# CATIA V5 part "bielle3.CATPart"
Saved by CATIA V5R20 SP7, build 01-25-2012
Part number: bielle3
Publications: "droite_bielle_3", "droite_pivot_3_2", "droite_pivot_3_0"
Bounding box of the stored display mesh (mm): x 0 to 0.5, y 0.96 to 2.4, z 0 to 2.63
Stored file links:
  U:\IAO\bielle3.CATPart
  U:\IAO\skl_brevet_iao.CATProduct
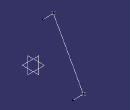
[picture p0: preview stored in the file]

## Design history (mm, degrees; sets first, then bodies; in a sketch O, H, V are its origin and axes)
Set1
  Point1 "point C": linked copy from another document
  Point2 "point D": linked copy from another document
Set2
  Line1 "droite_bielle_3": type PtPt, FirstPoint Point1, SecondPoint Point2
  Line2 "droite_pivot_3_2": type Normal, RefPoint Point1, RefSkin yz-plane, Start 0, End 0.5
  Line3 "droite_pivot_3_0": type Normal, RefPoint Point2, RefSkin yz-plane, Start 0, End 0.5
Body1 (main body)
